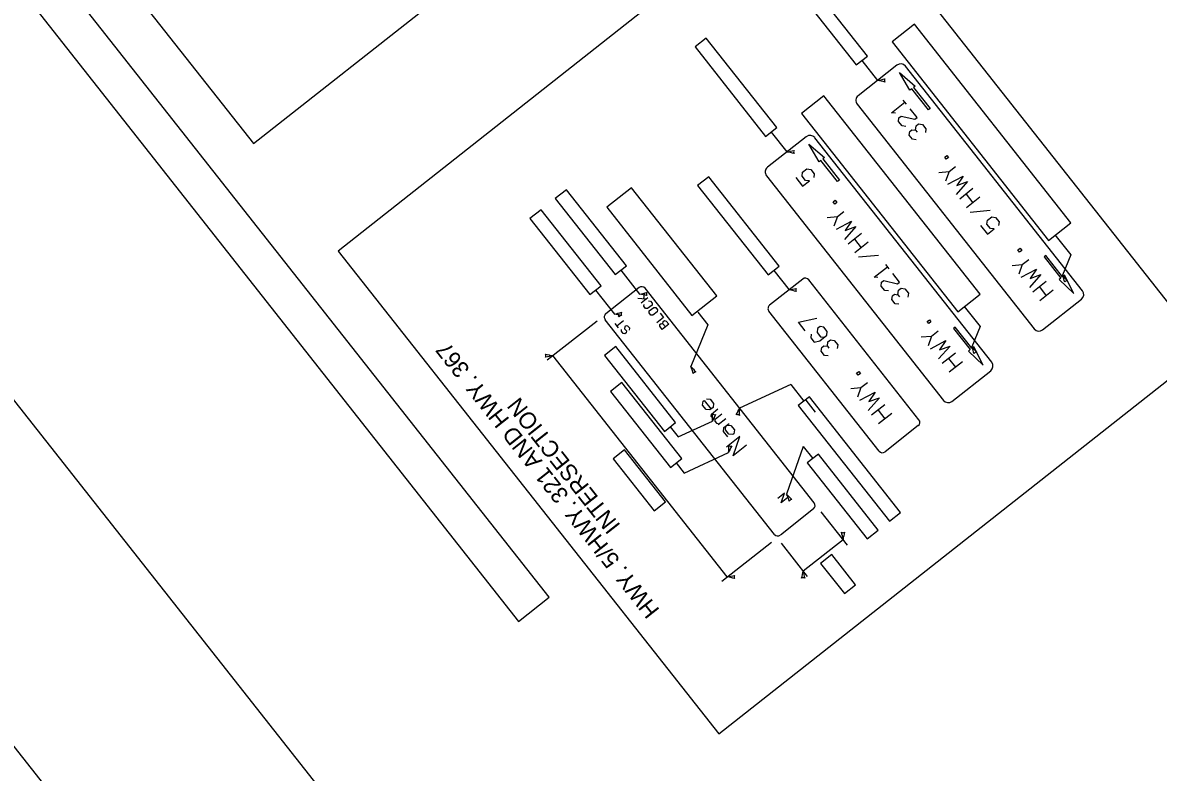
# Model space of a CAD drawing. Extents: x 671946 to 673995, y 1673066 to 1674936.
# Drawn here: x 672850 to 673404, y 1673780 to 1674146 of the extents above; entities that cross this region are included whole.
import ezdxf

# ---------------------------------------------------------------- set-up
doc = ezdxf.new("R2010")
doc.units = 0
for name, color, linetype in [('C-ANNO-SYMB', 7, 'Continuous'), ('Default', 7, 'Continuous'), ('G-ANNO-TTLB', 7, 'Continuous'), ('R_Border', 7, 'Continuous'), ('R_No Plot', 7, 'Continuous'), ('T_Drafting', 7, 'Continuous')]:
    doc.layers.add(name, color=color, linetype=linetype)

msp = doc.modelspace()

# ---------------------------------------------------------------- linework, layer by layer
at = {"layer": 'C-ANNO-SYMB'}
for points in [[(673106.47, 1673865.45), (672830.78, 1674215.15), (672815.79, 1674203.33), (673091.48, 1673853.63)], [(673188.26, 1674012.46), (673146.67, 1674065.21), (673134.57, 1674055.67), (673176.16, 1674002.92)]]:
    msp.add_lwpolyline(points, close=True, dxfattribs=at)
at = {"layer": 'Default'}
for points in [[(673261.79, 1674129.42), (673227.4, 1674173.05), (673221.95, 1674168.75), (673256.34, 1674125.13)], [(673361.08, 1674048.1), (673284.76, 1674144.91), (673273.86, 1674136.31), (673350.17, 1674039.51)], [(673217.53, 1674094.53), (673183.14, 1674138.16), (673177.69, 1674133.86), (673212.08, 1674090.24)], [(673316.82, 1674013.21), (673240.5, 1674110.01), (673229.6, 1674101.42), (673305.91, 1674004.61)], [(673218.8, 1674026.96), (673184.41, 1674070.58), (673178.96, 1674066.28), (673213.35, 1674022.66)], [(673144.17, 1674027.12), (673114.93, 1674064.21), (673109.48, 1674059.91), (673138.71, 1674022.83)], [(673131.82, 1674017.39), (673102.59, 1674054.47), (673097.14, 1674050.18), (673126.37, 1674013.1)], [(673168.19, 1673950.63), (673138.96, 1673987.71), (673133.51, 1673983.41), (673162.74, 1673946.33)], [(673171.18, 1673933.07), (673141.95, 1673970.15), (673136.5, 1673965.85), (673165.73, 1673928.77)], [(673277.99, 1673906.79), (673233.5, 1673963.23), (673228.04, 1673958.93), (673272.54, 1673902.49)], [(673163.26, 1673911.92), (673143.27, 1673937.28), (673137.81, 1673932.98), (673157.81, 1673907.62)], [(673267.09, 1673898.19), (673237.86, 1673935.27), (673232.41, 1673930.97), (673261.64, 1673893.89)], [(673256.02, 1673871.47), (673244.41, 1673886.2), (673238.96, 1673881.9), (673250.57, 1673867.17)]]:
    msp.add_lwpolyline(points, close=True, dxfattribs=at)
at = {"layer": 'G-ANNO-TTLB'}
msp.add_lwpolyline([(673177.78, 1673539.85), (672546.3, 1674340.87), (673064.6, 1674749.47), (673696.09, 1673948.45)], close=True, dxfattribs=at)
at = {"layer": 'R_No Plot'}
msp.add_lwpolyline([(672577.31, 1673066.46), (671945.82, 1673867.48), (672464.13, 1674276.09), (673095.61, 1673475.07)], close=True, dxfattribs=at)
at = {"layer": 'T_Drafting'}
for p, q in [((672710.52, 1674406.05), (672962.28, 1674086.7)), ((672962.28, 1674086.7), (673199.76, 1674273.91)), ((673241.05, 1674221.53), (673003.58, 1674034.32)), ((673426.78, 1673985.94), (673241.05, 1674221.53)), ((673259.07, 1674127.28), (673266.76, 1674117.52)), ((673276.23, 1674124.99), (673257.28, 1674110.05)), ((673366.73, 1674014.91), (673280.33, 1674124.5)), ((673256.8, 1674105.95), (673343.2, 1673996.36)), ((673280.9, 1674105.88), (673279.29, 1674107.92)), ((673285.23, 1674093.25), (673286, 1674092.28)), ((673231.97, 1674090.1), (673213.02, 1674075.16)), ((673214.81, 1674092.38), (673222.5, 1674082.63)), ((673322.47, 1673980.02), (673236.07, 1674089.61)), ((673212.54, 1674071.06), (673298.94, 1673961.47)), ((673301.63, 1674073.09), (673304.79, 1674075.58)), ((673313.31, 1674064.77), (673306.83, 1674059.66)), ((673309.95, 1674062.11), (673313.28, 1674057.88)), ((673316.65, 1674060.53), (673310.17, 1674055.43)), ((673247.15, 1674051.15), (673250.31, 1674053.65)), ((673321.76, 1674054.06), (673311.94, 1674053.18)), ((673258.84, 1674042.83), (673252.36, 1674037.73)), ((673255.47, 1674040.18), (673258.81, 1674035.94)), ((673262.18, 1674038.6), (673255.7, 1674033.49)), ((673353.32, 1674042.16), (673361.01, 1674032.41)), ((673003.58, 1674034.32), (673189.31, 1673798.72)), ((673267.28, 1674032.12), (673257.47, 1674031.25)), ((673361.01, 1674032.41), (673357.01, 1674022.52)), ((673272.39, 1674025.64), (673270.78, 1674027.68)), ((673337.38, 1674027.74), (673340.54, 1674030.23)), ((673141.44, 1674024.98), (673150.66, 1674013.28)), ((673230.26, 1674020.64), (673214.07, 1674007.87)), ((673216.07, 1674024.81), (673223.54, 1674015.34)), ((673129.1, 1674015.24), (673138.31, 1674003.55)), ((673150.39, 1674016.49), (673134.19, 1674003.72)), ((673235.85, 1673911.41), (673153.28, 1674016.14)), ((673286.97, 1673952.03), (673233.16, 1674020.29)), ((673349.06, 1674019.42), (673342.58, 1674014.31)), ((673345.7, 1674016.77), (673349.03, 1674012.53)), ((673352.4, 1674015.19), (673345.92, 1674010.08)), ((673153.62, 1674010.76), (673149.76, 1674011.15)), ((673151.43, 1674009.03), (673154.67, 1674011.59)), ((673152.69, 1674010.85), (673153, 1674013.7)), ((673276.72, 1674013.01), (673277.49, 1674012.04)), ((673347.29, 1673995.87), (673366.24, 1674010.81)), ((673179.05, 1674004.53), (673183.94, 1673998.33)), ((673267.54, 1673936.71), (673213.72, 1674004.97)), ((673309.06, 1674007.27), (673316.75, 1673997.52)), ((673105.58, 1673981.16), (673129.87, 1674000.31)), ((673216.41, 1673896.09), (673133.85, 1674000.82)), ((673140.42, 1673996.82), (673138.74, 1673998.96)), ((673139.58, 1673997.89), (673142.82, 1674000.45)), ((673163.23, 1673997.32), (673162.02, 1673998.85)), ((673183.94, 1673998.33), (673175.69, 1673977.99)), ((673293.12, 1673992.85), (673296.28, 1673995.34)), ((673316.75, 1673997.52), (673312.75, 1673987.63)), ((673242.25, 1673987.84), (673243.02, 1673986.87)), ((673193.4, 1673875.32), (673108.28, 1673983.29)), ((673189.31, 1673798.72), (673426.78, 1673985.94)), ((673304.8, 1673984.53), (673298.33, 1673979.42)), ((673301.44, 1673981.87), (673304.77, 1673977.64)), ((673308.14, 1673980.29), (673301.66, 1673975.19)), ((673303.04, 1673960.98), (673321.98, 1673975.92)), ((673224.41, 1673969.15), (673199.36, 1673957.7)), ((673224.41, 1673969.15), (673230.77, 1673961.08)), ((673258.65, 1673967.68), (673261.81, 1673970.17)), ((673231.75, 1673961.53), (673236.36, 1673955.69)), ((673187.59, 1673952.34), (673190.76, 1673954.83)), ((673270.33, 1673959.36), (673263.86, 1673954.25)), ((673266.97, 1673956.7), (673270.3, 1673952.47)), ((673273.67, 1673955.12), (673267.19, 1673950.01)), ((673165.61, 1673948.59), (673169.5, 1673943.66)), ((673169.5, 1673943.66), (673186.16, 1673951.28)), ((673192.69, 1673952.39), (673189.01, 1673949.49)), ((673286.63, 1673949.14), (673270.43, 1673936.37)), ((673230.52, 1673938.97), (673222.39, 1673915.67)), ((673230.52, 1673938.97), (673235.13, 1673933.12)), ((673172.33, 1673926.01), (673194.08, 1673935.95)), ((673168.46, 1673930.92), (673172.33, 1673926.01)), ((673235.51, 1673908.52), (673219.31, 1673895.75)), ((673252.02, 1673890.9), (673239.25, 1673907.09)), ((673230.46, 1673878.28), (673249.89, 1673893.6)), ((673190.7, 1673873.19), (673214.99, 1673892.34)), ((673232.59, 1673875.58), (673219.82, 1673891.77))]:
    msp.add_line(p, q, dxfattribs=at)
for points in [[(673291.54, 1674103.13), (673283.41, 1674113.44), (673282.56, 1674112.76), (673277.53, 1674121.33), (673285.13, 1674114.79), (673284.27, 1674114.12), (673292.4, 1674103.81)], [(673247.28, 1674068.24), (673239.15, 1674078.55), (673238.3, 1674077.87), (673233.27, 1674086.44), (673240.87, 1674079.9), (673240.01, 1674079.22), (673248.14, 1674068.92)], [(673348.08, 1674031.41), (673356.2, 1674021.11), (673355.35, 1674020.43), (673362.5, 1674013.54), (673357.92, 1674022.46), (673357.06, 1674021.78), (673348.94, 1674032.09)], [(673303.82, 1673996.52), (673311.95, 1673986.21), (673311.09, 1673985.54), (673318.24, 1673978.65), (673313.66, 1673987.57), (673312.8, 1673986.89), (673304.68, 1673997.2)]]:
    msp.add_lwpolyline(points, close=True, dxfattribs=at)
for points in [[(673275.44, 1674101.58), (673273.62, 1674101.79), (673280.1, 1674106.9)], [(673280.55, 1674095.1), (673278.73, 1674095.32), (673277.04, 1674097.46), (673277.21, 1674099.33), (673278.28, 1674100.18), (673284.99, 1674098.6), (673286.01, 1674099.4), (673282.67, 1674103.64)], [(673285.66, 1674088.62), (673283.83, 1674088.84), (673282.22, 1674090.88), (673282.48, 1674092.65), (673283.55, 1674093.5), (673285.23, 1674093.25), (673285.53, 1674095.39), (673286.76, 1674096.35), (673288.62, 1674096.09), (673290.31, 1674093.95), (673290.1, 1674092.12)], [(673300.31, 1674079.16), (673299.51, 1674080.18), (673300.53, 1674080.99), (673301.33, 1674079.97), (673300.31, 1674079.16)], [(673226.83, 1674070.12), (673230.16, 1674065.88), (673233.48, 1674068.5), (673231.6, 1674068.67), (673229.91, 1674070.81), (673230.14, 1674072.73), (673232.28, 1674074.42), (673234.15, 1674074.15), (673235.84, 1674072.01), (673235.62, 1674070.19)], [(673296.62, 1674072.62), (673301.63, 1674073.09), (673299.96, 1674068.38)], [(673301.12, 1674066.9), (673308.53, 1674070.84), (673305.49, 1674066.29), (673310.62, 1674068.19), (673305.07, 1674061.91)], [(673245.84, 1674057.23), (673245.03, 1674058.25), (673246.05, 1674059.05), (673246.86, 1674058.03), (673245.84, 1674057.23)], [(673242.15, 1674050.68), (673247.15, 1674051.15), (673245.48, 1674046.45)], [(673246.65, 1674044.97), (673254.05, 1674048.9), (673251.02, 1674044.36), (673256.15, 1674046.25), (673250.59, 1674039.97)], [(673317.05, 1674046.7), (673320.39, 1674042.47), (673323.7, 1674045.08), (673321.83, 1674045.26), (673320.14, 1674047.4), (673320.36, 1674049.32), (673322.51, 1674051.01), (673324.37, 1674050.74), (673326.06, 1674048.6), (673325.84, 1674046.77)], [(673336.06, 1674033.82), (673335.25, 1674034.84), (673336.28, 1674035.64), (673337.08, 1674034.62), (673336.06, 1674033.82)], [(673266.93, 1674021.34), (673265.11, 1674021.56), (673271.59, 1674026.66)], [(673332.37, 1674027.27), (673337.38, 1674027.74), (673335.71, 1674023.04)], [(673272.04, 1674014.86), (673270.22, 1674015.08), (673268.53, 1674017.22), (673268.7, 1674019.09), (673269.77, 1674019.94), (673276.48, 1674018.36), (673277.5, 1674019.16), (673274.16, 1674023.4)], [(673336.87, 1674021.56), (673344.28, 1674025.49), (673341.24, 1674020.95), (673346.37, 1674022.84), (673340.82, 1674016.56)], [(673277.15, 1674008.38), (673275.32, 1674008.6), (673273.71, 1674010.64), (673273.97, 1674012.41), (673275.04, 1674013.26), (673276.72, 1674013.01), (673277.02, 1674015.15), (673278.25, 1674016.12), (673280.11, 1674015.85), (673281.8, 1674013.71), (673281.59, 1674011.88)], [(673155.04, 1674010.06), (673155.98, 1674009.93), (673156.82, 1674008.86), (673156.71, 1674007.95), (673154.49, 1674006.2), (673153.58, 1674006.3), (673152.74, 1674007.38), (673152.83, 1674008.31)], [(673156.14, 1674003.07), (673155.29, 1674004.14), (673155.38, 1674005.07), (673157.6, 1674006.82), (673158.53, 1674006.69), (673159.37, 1674005.62), (673159.27, 1674004.71), (673157.05, 1674002.96), (673156.14, 1674003.07)], [(673160.66, 1674003.99), (673162.33, 1674001.87), (673159.09, 1673999.32)], [(673140.6, 1674002.21), (673140.2, 1674002.72), (673140.71, 1674003.12), (673141.11, 1674002.61), (673140.6, 1674002.21)], [(673164.88, 1673998.63), (673161.65, 1673996.08), (673160.44, 1673997.61), (673160.59, 1673998.47), (673161.12, 1673998.89), (673162.02, 1673998.85), (673162.14, 1673999.9), (673162.73, 1674000.37), (673163.68, 1674000.16), (673164.88, 1673998.63)], [(673231.44, 1673995.36), (673228.11, 1673999.6), (673237.12, 1674001.49)], [(673291.8, 1673998.92), (673291, 1673999.95), (673292.02, 1674000.75), (673292.82, 1673999.73), (673291.8, 1673998.92)], [(673145.71, 1673995.73), (673145.81, 1673996.64), (673144.97, 1673997.72), (673144.04, 1673997.85), (673143.5, 1673997.43), (673143.34, 1673996.43), (673144.18, 1673995.36), (673144.02, 1673994.41), (673143.49, 1673993.98), (673142.58, 1673994.09), (673141.73, 1673995.16), (673141.82, 1673996.1)], [(673234.35, 1673993.77), (673234.18, 1673991.89), (673235.75, 1673989.9), (673238.64, 1673990.53), (673242.01, 1673993.19), (673242.22, 1673995.01), (673240.54, 1673997.15), (673238.67, 1673997.42), (673237.5, 1673996.5), (673237.27, 1673994.58), (673238.96, 1673992.44), (673240.84, 1673992.26)], [(673288.11, 1673992.38), (673293.12, 1673992.85), (673291.45, 1673988.14)], [(673242.68, 1673983.21), (673240.85, 1673983.43), (673239.24, 1673985.47), (673239.5, 1673987.24), (673240.57, 1673988.08), (673242.25, 1673987.84), (673242.55, 1673989.98), (673243.78, 1673990.94), (673245.64, 1673990.68), (673247.33, 1673988.53), (673247.12, 1673986.71)], [(673292.62, 1673986.66), (673300.02, 1673990.6), (673296.98, 1673986.06), (673302.11, 1673987.95), (673296.56, 1673981.67)], [(673257.33, 1673973.75), (673256.53, 1673974.77), (673257.55, 1673975.58), (673258.35, 1673974.56), (673257.33, 1673973.75)], [(673253.64, 1673967.2), (673258.65, 1673967.68), (673256.98, 1673962.97)], [(673258.15, 1673961.49), (673265.55, 1673965.43), (673262.51, 1673960.88), (673267.64, 1673962.77), (673262.09, 1673956.49)], [(673183.22, 1673962.29), (673185.08, 1673962.03), (673186.77, 1673959.88), (673186.56, 1673958.06), (673184.93, 1673956.77), (673183.1, 1673956.99), (673181.41, 1673959.13), (673181.59, 1673961.01), (673182.15, 1673961.45), (673185.49, 1673957.21)], [(673189.52, 1673949.89), (673188.49, 1673950.15), (673187.56, 1673951.33), (673187.59, 1673952.34), (673186.64, 1673952.5), (673185.63, 1673953.77), (673185.66, 1673954.79), (673188.82, 1673957.28)], [(673193.64, 1673943.62), (673191.55, 1673946.28), (673191.72, 1673948.15), (673194.37, 1673950.24)], [(673193.35, 1673949.44), (673195.22, 1673949.17), (673196.91, 1673947.03), (673196.69, 1673945.2), (673196.13, 1673944.76), (673194.26, 1673944.94), (673192.57, 1673947.08), (673192.79, 1673949)], [(673202.82, 1673939.53), (673196.34, 1673934.42), (673199.48, 1673943.76), (673193, 1673938.66)], [(673223.02, 1673914.06), (673219.78, 1673911.5), (673221.35, 1673916.17), (673218.11, 1673913.62)]]:
    msp.add_lwpolyline(points, dxfattribs=at)
for centre, radius, start, end in [((673278.04, 1674122.7), 2.92, 38.2505, 128.2505), ((673262.58, 1674144.09), 26.9, 278.933, 286.6711), ((673262.88, 1674090.9), 26.9, 73.9782, 81.7163), ((673271.56, 1674117.55), 1.49, 148.4773, 212.172), ((673259.09, 1674107.76), 2.92, 128.2505, 218.2505), ((673233.78, 1674087.81), 2.92, 38.2505, 128.2505), ((673218.32, 1674109.2), 26.9, 278.933, 286.6711), ((673218.62, 1674056.01), 26.9, 73.9782, 81.7163), ((673227.3, 1674082.65), 1.49, 148.4773, 212.172), ((673214.83, 1674072.87), 2.92, 128.2505, 218.2505), ((673231.54, 1674019.02), 2.06, 38.2505, 128.2505), ((673378.21, 1674039.06), 26.9, 217.9568, 225.6949), ((673331.85, 1674013), 26.9, 13.002, 20.7402), ((673151.66, 1674014.87), 2.06, 38.2505, 128.2505), ((673219.63, 1674041.95), 26.9, 278.3549, 286.093), ((673219.4, 1673988.76), 26.9, 73.4002, 81.1383), ((673228.35, 1674015.32), 1.49, 147.8993, 211.5939), ((673359.36, 1674018.33), 1.49, 87.5012, 151.1958), ((673364.44, 1674013.1), 2.92, 308.2505, 38.2505), ((673145.97, 1674039.77), 26.9, 280.0336, 287.7717), ((673147.29, 1673986.6), 26.9, 75.0789, 82.817), ((673155.46, 1674013.4), 1.49, 149.578, 213.2726), ((673133.63, 1674030.04), 26.9, 280.0336, 287.7717), ((673143.12, 1674003.67), 1.49, 149.578, 213.2726), ((673215.34, 1674006.25), 2.06, 128.2505, 218.2505), ((673135.47, 1674002.1), 2.06, 128.2505, 218.2505), ((673134.95, 1673976.87), 26.9, 75.0789, 82.817), ((673345.49, 1673998.16), 2.92, 218.2505, 308.2505), ((673333.78, 1674004.39), 26.9, 218.5447, 226.2828), ((673287.69, 1673977.85), 26.9, 13.59, 21.3281), ((673103.47, 1673983.25), 1.49, 328.6568, 32.3514), ((673112.07, 1674009.92), 26.9, 254.1577, 261.8958), ((673112.54, 1673956.73), 26.9, 99.1124, 106.8505), ((673315.15, 1673983.46), 1.49, 88.0891, 151.7837), ((673196.7, 1673994.79), 26.9, 218.6569, 226.395), ((673150.66, 1673968.16), 26.9, 13.7021, 21.4403), ((673320.18, 1673978.21), 2.92, 308.2505, 38.2505), ((673178.1, 1673973.83), 1.49, 88.2013, 151.8959), ((673301.23, 1673963.27), 2.92, 218.2505, 308.2505), ((673159.33, 1673953.17), 26.9, 355.9712, 3.7093), ((673211.23, 1673941.53), 26.9, 151.0165, 158.7546), ((673187.21, 1673955.97), 1.49, 225.5156, 289.2102), ((673174.35, 1673967.6), 26.9, 330.653, 338.3911), ((673198.28, 1673953.02), 1.49, 45.1521, 108.8468), ((673226.18, 1673955.64), 26.9, 175.6078, 183.3459), ((673285.35, 1673950.75), 2.06, 308.2505, 38.2505), ((673167.25, 1673937.84), 26.9, 355.9712, 3.7093), ((673219.15, 1673926.21), 26.9, 151.0165, 158.7546), ((673195.13, 1673940.64), 1.49, 225.5156, 289.2102), ((673269.16, 1673937.99), 2.06, 218.2505, 308.2505), ((673242.54, 1673933.48), 26.9, 221.4771, 229.2152), ((673197.87, 1673904.62), 26.9, 16.5224, 24.2605), ((673225, 1673911.63), 1.49, 91.0215, 154.7161), ((673234.23, 1673910.14), 2.06, 308.2505, 38.2505), ((673218.03, 1673897.37), 2.06, 218.2505, 308.2505), ((673249.88, 1673898.4), 1.49, 238.2675, 301.9621), ((673223.31, 1673889.52), 26.9, 8.7231, 16.4612), ((673276.5, 1673889.63), 26.9, 163.7683, 171.5065), ((673203.91, 1673882.58), 26.9, 343.0462, 350.7843), ((673257.09, 1673882.02), 26.9, 188.0009, 195.7391), ((673189.36, 1673901.91), 26.9, 278.6398, 286.3779), ((673189.39, 1673848.73), 26.9, 73.685, 81.4231), ((673198.2, 1673875.32), 1.49, 148.1841, 211.8788), ((673230.41, 1673873.47), 1.49, 57.5453, 121.2399)]:
    msp.add_arc(centre, radius, start, end, dxfattribs=at)

# ---------------------------------------------------------------- texts
at = {"layer": 'R_Border'}
for s, p in [('HWY. 5/HWY. 321 AND HWY. 367', (673160.72, 1673859.22)), ('INTERSECTION', (673141.64, 1673900.41))]:
    msp.add_text(s, height=8.082, rotation=128.2505, dxfattribs=at).set_placement(p)

doc.saveas('drawing.dxf')
